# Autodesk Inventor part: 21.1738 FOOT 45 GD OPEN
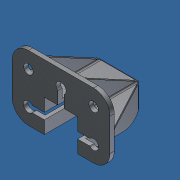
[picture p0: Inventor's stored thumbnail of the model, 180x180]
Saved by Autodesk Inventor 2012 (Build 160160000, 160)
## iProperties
Created: 2007-04
Part Number: 21.1738 FOOT 45 GD OPEN
Material: Aluminum-6061
Document SubType Name: Modeling
Designer: Andy Moles
Density: 2.71 g/cm^3
Mass: 314.035 g
Surface Area: 529.929 cm^2
Volume: 115.88 cm^3
Author: Andy Moles
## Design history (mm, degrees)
feature "Base1"
sketch "Sketch1"
  geometry: C1 r 4.5 at (90, -22.5) reference; C2 r 4.5 at (0, -22.5) reference; 3 further points
  constraints: 2 coincident
hole "Hole1" sketch "Sketch1" at (90, -22.5), (0, -22.5) diameter "d0" = 13; stored, may be unused: countersink angle "d4" = 90 deg, drill point angle "d6" = 118 deg; dims "d1" = 6, "d2" = 4, "d3" = 2, "d5" = 8
body "Solid1"
